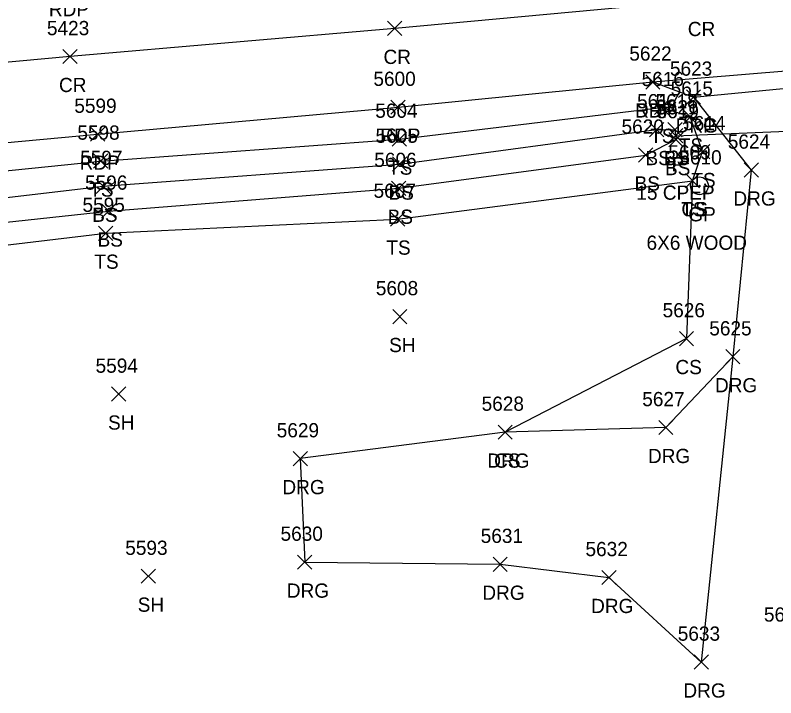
# Model space of a CAD drawing. Extents: x 1443912 to 1445411, y 621446 to 623693.
# Drawn here: x 1444289.1 to 1444396, y 622435.9 to 622531.9 of the extents above; entities that cross this region are included whole.
import ezdxf

# ---------------------------------------------------------------- set-up
doc = ezdxf.new("R2010")
doc.units = 0
for name, color, linetype in [('D_A', 7, 'Continuous'), ('D_C', 7, 'Continuous'), ('D_I', 7, 'Continuous'), ('D_TIC', 7, 'Continuous'), ('DCP', 7, 'Continuous'), ('L_A', 7, 'Continuous'), ('L_I', 7, 'Continuous'), ('L_TIC', 7, 'Continuous'), ('LELB', 7, 'Continuous'), ('P_A', 7, 'Continuous'), ('P_I', 7, 'Continuous'), ('P_TIC', 7, 'Continuous'), ('PET', 7, 'Continuous'), ('PRC', 7, 'Continuous'), ('R_A', 7, 'Continuous'), ('R_C', 7, 'Continuous'), ('R_I', 7, 'Continuous'), ('R_TIC', 7, 'Continuous'), ('RDG', 7, 'Continuous'), ('RDP', 7, 'Continuous'), ('RGP', 7, 'Continuous')]:
    doc.layers.add(name, color=color, linetype=linetype)

msp = doc.modelspace()

# ---------------------------------------------------------------- linework, layer by layer
at = {"layer": 'D_TIC'}
for points in [[(1444380.93, 622513.94), (1444382.93, 622515.94)], [(1444382.93, 622513.94), (1444380.93, 622515.94)]]:
    msp.add_lwpolyline(points, dxfattribs=at)
at = {"layer": 'DCP'}
msp.add_lwpolyline([(1444381.93, 622514.94), (1444423.13, 622516.67)], dxfattribs=at)
at = {"layer": 'L_TIC'}
for points in [[(1444378.93, 622517.92), (1444380.93, 622519.92)], [(1444380.93, 622517.92), (1444378.93, 622519.92)], [(1444378.93, 622517.92), (1444380.93, 622519.92)], [(1444380.93, 622517.92), (1444378.93, 622519.92)], [(1444382.95, 622516.58), (1444384.95, 622518.58)], [(1444384.95, 622516.58), (1444382.95, 622518.58)], [(1444378.23, 622514.8), (1444380.23, 622516.8)], [(1444380.23, 622514.8), (1444378.23, 622516.8)], [(1444380.82, 622514.79), (1444382.82, 622516.79)], [(1444382.82, 622514.79), (1444380.82, 622516.79)], [(1444342.08, 622513.46), (1444344.08, 622515.46)], [(1444344.08, 622513.46), (1444342.08, 622515.46)], [(1444380.97, 622513.39), (1444382.97, 622515.39)], [(1444382.97, 622513.39), (1444380.97, 622515.39)], [(1444384.71, 622511.71), (1444386.71, 622513.71)], [(1444386.71, 622511.71), (1444384.71, 622513.71)], [(1444300.08, 622510.38), (1444302.08, 622512.38)], [(1444302.08, 622510.38), (1444300.08, 622512.38)], [(1444376.7, 622511.23), (1444378.7, 622513.23)], [(1444378.7, 622511.23), (1444376.7, 622513.23)], [(1444376.7, 622511.23), (1444378.7, 622513.23)], [(1444378.7, 622511.23), (1444376.7, 622513.23)], [(1444342.11, 622509.95), (1444344.11, 622511.95)], [(1444344.11, 622509.95), (1444342.11, 622511.95)], [(1444383.28, 622507.61), (1444385.28, 622509.61)], [(1444385.28, 622507.61), (1444383.28, 622509.61)], [(1444383.28, 622507.61), (1444385.28, 622509.61)], [(1444385.28, 622507.61), (1444383.28, 622509.61)], [(1444300.47, 622506.83), (1444302.47, 622508.83)], [(1444302.47, 622506.83), (1444300.47, 622508.83)], [(1444341.99, 622506.55), (1444343.99, 622508.55)], [(1444343.99, 622506.55), (1444341.99, 622508.55)], [(1444301.22, 622503.35), (1444303.22, 622505.35)], [(1444303.22, 622503.35), (1444301.22, 622505.35)], [(1444341.84, 622502.21), (1444343.84, 622504.21)], [(1444343.84, 622502.21), (1444341.84, 622504.21)], [(1444300.8, 622500.23), (1444302.8, 622502.23)], [(1444302.8, 622500.23), (1444300.8, 622502.23)], [(1444342.15, 622488.51), (1444344.15, 622490.51)], [(1444344.15, 622488.51), (1444342.15, 622490.51)], [(1444382.44, 622485.41), (1444384.44, 622487.41)], [(1444384.44, 622485.41), (1444382.44, 622487.41)], [(1444302.64, 622477.61), (1444304.64, 622479.61)], [(1444304.64, 622477.61), (1444302.64, 622479.61)], [(1444356.95, 622472.26), (1444358.95, 622474.26)], [(1444358.95, 622472.26), (1444356.95, 622474.26)], [(1444306.81, 622452), (1444308.81, 622454)], [(1444308.81, 622452), (1444306.81, 622454)]]:
    msp.add_lwpolyline(points, dxfattribs=at)
at = {"layer": 'LELB'}
for points in [[(1444115.2, 622494.89), (1444168.95, 622497.42), (1444211.15, 622502.44), (1444251.83, 622506.34), (1444301.08, 622511.38), (1444343.08, 622514.46), (1444379.93, 622518.92)], [(1444185.15, 622436.84), (1444194.75, 622460.13), (1444204.54, 622478.89), (1444215.9, 622488.4), (1444251.49, 622495.26), (1444301.8, 622501.23), (1444342.84, 622503.21), (1444384.28, 622508.61), (1444385.71, 622512.71), (1444383.95, 622517.58), (1444379.93, 622518.92)], [(1444137.9, 622478.21), (1444124.84, 622486.58), (1444113.1, 622488.96), (1444113.21, 622490.09), (1444168.95, 622494.43), (1444215.67, 622499.54), (1444251.54, 622502), (1444301.47, 622507.83), (1444343.11, 622510.95), (1444379.23, 622515.8), (1444381.82, 622515.79), (1444381.97, 622514.39), (1444377.7, 622512.23)], [(1444185.61, 622491.47), (1444215.88, 622495.41), (1444251.8, 622498.9), (1444302.22, 622504.35), (1444342.99, 622507.55), (1444377.7, 622512.23)], [(1444384.28, 622508.61), (1444383.44, 622486.41), (1444357.95, 622473.26)]]:
    msp.add_lwpolyline(points, dxfattribs=at)
at = {"layer": 'P_TIC'}
for points in [[(1444341.42, 622529.03), (1444343.42, 622531.03)], [(1444343.42, 622529.03), (1444341.42, 622531.03)], [(1444295.8, 622525.08), (1444297.8, 622527.08)], [(1444297.8, 622525.08), (1444295.8, 622527.08)], [(1444377.71, 622521.5), (1444379.71, 622523.5)], [(1444379.71, 622521.5), (1444377.71, 622523.5)], [(1444341.9, 622517.95), (1444343.9, 622519.95)], [(1444343.9, 622517.95), (1444341.9, 622519.95)], [(1444299.66, 622514.16), (1444301.66, 622516.16)], [(1444301.66, 622514.16), (1444299.66, 622516.16)]]:
    msp.add_lwpolyline(points, dxfattribs=at)
at = {"layer": 'PET'}
msp.add_lwpolyline([(1443922.89, 622481.78), (1443964.16, 622485.92), (1444013.47, 622490.18), (1444063.08, 622494.61), (1444083.54, 622496.56), (1444116.52, 622499.25), (1444168.09, 622503.58), (1444210.27, 622507.18), (1444250.99, 622510.56), (1444300.66, 622515.16), (1444342.9, 622518.95), (1444378.71, 622522.5), (1444430.26, 622526.78), (1444460.19, 622529.88), (1444494.98, 622532.7), (1444537.07, 622536.56), (1444563.09, 622539.1), (1444595.4, 622542.11), (1444628.15, 622544.68), (1444676.42, 622546.88), (1444682.73, 622544.1), (1444699.24, 622535.04), (1444703.98, 622527.2), (1444703.26, 622510.63)], dxfattribs=at)
at = {"layer": 'PRC'}
msp.add_lwpolyline([(1444719.77, 622561.99), (1444681.72, 622559.72), (1444650.83, 622557.58), (1444613.8, 622554.84), (1444583.05, 622552.28), (1444545.98, 622548.57), (1444490.19, 622543.66), (1444448.69, 622540.02), (1444415.77, 622536.99), (1444385.19, 622533.95), (1444342.42, 622530.03), (1444296.8, 622526.08), (1444247.95, 622521.6), (1444210.22, 622518.45), (1444165.33, 622514.18), (1444110.47, 622509.68), (1444063.9, 622505.59), (1444012.84, 622501.59), (1443966.33, 622497.17), (1443919.63, 622492.61)], dxfattribs=at)
at = {"layer": 'R_TIC'}
for points in [[(1444377.71, 622521.5), (1444379.71, 622523.5)], [(1444379.71, 622521.5), (1444377.71, 622523.5)], [(1444383.42, 622519.38), (1444385.42, 622521.38)], [(1444385.42, 622519.38), (1444383.42, 622521.38)], [(1444383.42, 622519.38), (1444385.42, 622521.38)], [(1444385.42, 622519.38), (1444383.42, 622521.38)], [(1444391.55, 622509.12), (1444393.55, 622511.12)], [(1444393.55, 622509.12), (1444391.55, 622511.12)], [(1444388.95, 622482.86), (1444390.95, 622484.86)], [(1444390.95, 622482.86), (1444388.95, 622484.86)], [(1444388.95, 622482.86), (1444390.95, 622484.86)], [(1444390.95, 622482.86), (1444388.95, 622484.86)], [(1444379.53, 622472.91), (1444381.53, 622474.91)], [(1444381.53, 622472.91), (1444379.53, 622474.91)], [(1444356.95, 622472.26), (1444358.95, 622474.26)], [(1444358.95, 622472.26), (1444356.95, 622474.26)], [(1444328.16, 622468.53), (1444330.16, 622470.53)], [(1444330.16, 622468.53), (1444328.16, 622470.53)], [(1444328.77, 622453.98), (1444330.77, 622455.98)], [(1444330.77, 622453.98), (1444328.77, 622455.98)], [(1444356.25, 622453.68), (1444358.25, 622455.68)], [(1444358.25, 622453.68), (1444356.25, 622455.68)], [(1444371.54, 622451.82), (1444373.54, 622453.82)], [(1444373.54, 622451.82), (1444371.54, 622453.82)], [(1444384.51, 622439.93), (1444386.51, 622441.93)], [(1444386.51, 622439.93), (1444384.51, 622441.93)], [(1444384.51, 622439.93), (1444386.51, 622441.93)], [(1444386.51, 622439.93), (1444384.51, 622441.93)]]:
    msp.add_lwpolyline(points, dxfattribs=at)
at = {"layer": 'RDG'}
for points in [[(1444384.42, 622520.38), (1444392.55, 622510.12), (1444389.95, 622483.86), (1444385.51, 622440.93)], [(1444389.95, 622483.86), (1444380.53, 622473.91), (1444357.95, 622473.26), (1444329.16, 622469.53), (1444329.77, 622454.98), (1444357.25, 622454.68), (1444372.54, 622452.82), (1444385.51, 622440.93)]]:
    msp.add_lwpolyline(points, dxfattribs=at)
at = {"layer": 'RDP'}
msp.add_lwpolyline([(1444378.71, 622522.5), (1444384.42, 622520.38), (1444401.39, 622522.01), (1444424.34, 622524.73), (1444430.26, 622526.78)], dxfattribs=at)
at = {"layer": 'RGP'}
msp.add_line((1444385.26, 622507.9), (1444385.26, 622507.9), dxfattribs=at)
for radius in [1.25, 0.0833]:
    msp.add_circle((1444385.26, 622507.9), radius, dxfattribs=at)

# ---------------------------------------------------------------- texts
at = {"layer": 'D_A'}
msp.add_text('P', height=2, dxfattribs=at).set_placement((1444381.31, 622509.94))
at = {"layer": 'D_C'}
msp.add_text('15 CPEP', height=2, dxfattribs=at).set_placement((1444376.39, 622505.94))
at = {"layer": 'D_I'}
msp.add_text('5621', height=2, dxfattribs=at).set_placement((1444379.19, 622517.94))
at = {"layer": 'L_A'}
for s, p in [('TS', (1444378.34, 622513.92)), ('TS', (1444378.34, 622513.92)), ('TS', (1444382.36, 622512.58)), ('BS', (1444377.67, 622510.8)), ('BS', (1444380.26, 622510.79)), ('TS', (1444341.49, 622509.46)), ('BS', (1444380.41, 622509.39)), ('BS', (1444376.14, 622507.23)), ('BS', (1444376.14, 622507.23)), ('TS', (1444384.12, 622507.71)), ('TS', (1444299.49, 622506.38)), ('BS', (1444341.56, 622505.95)), ('BS', (1444299.91, 622502.83)), ('TS', (1444382.69, 622503.61)), ('CS', (1444382.72, 622503.61)), ('BS', (1444341.43, 622502.55)), ('BS', (1444300.66, 622499.35)), ('TS', (1444341.25, 622498.21)), ('TS', (1444300.21, 622496.23)), ('SH', (1444341.64, 622484.51)), ('CS', (1444381.88, 622481.41)), ('SH', (1444302.13, 622473.61)), ('CS', (1444356.39, 622468.26)), ('SH', (1444306.3, 622448))]:
    msp.add_text(s, height=2, dxfattribs=at).set_placement(p)
at = {"layer": 'L_I'}
for s, p in [('5616', (1444377.13, 622521.92)), ('5616', (1444377.13, 622521.92)), ('5615', (1444381.21, 622520.58)), ('5617', (1444376.49, 622518.8)), ('5618', (1444379.08, 622518.79)), ('5604', (1444339.69, 622517.46)), ('5619', (1444379.23, 622517.39)), ('5614', (1444382.97, 622515.71)), ('5620', (1444374.31, 622515.23)), ('5620', (1444374.31, 622515.23)), ('5598', (1444297.82, 622514.38)), ('5605', (1444339.73, 622513.95)), ('5609', (1444380.89, 622511.61)), ('5609', (1444380.89, 622511.61)), ('5597', (1444298.21, 622510.83)), ('5606', (1444339.55, 622510.55)), ('5596', (1444298.9, 622507.35)), ('5607', (1444339.45, 622506.21)), ('5595', (1444298.54, 622504.23)), ('5608', (1444339.77, 622492.51)), ('5626', (1444380.08, 622489.41)), ('5594', (1444300.38, 622481.61)), ('5628', (1444354.64, 622476.26)), ('5593', (1444304.55, 622456))]:
    msp.add_text(s, height=2, dxfattribs=at).set_placement(p)
at = {"layer": 'P_A'}
for s, p in [('RDP', (1444293.82, 622531.74)), ('CR', (1444383.62, 622528.95)), ('CR', (1444340.85, 622525.03)), ('CR', (1444295.24, 622521.08)), ('RDP', (1444376.2, 622517.5)), ('RDP', (1444340.39, 622513.95)), ('RDP', (1444298.14, 622510.16))]:
    msp.add_text(s, height=2, dxfattribs=at).set_placement(p)
at = {"layer": 'P_I'}
for s, p in [('5423', (1444293.54, 622529.08)), ('5622', (1444375.4, 622525.5)), ('5600', (1444339.43, 622521.95)), ('5599', (1444297.39, 622518.16)), ('5634', (1444394.32, 622446.62))]:
    msp.add_text(s, height=2, dxfattribs=at).set_placement(p)
at = {"layer": 'R_A'}
for s, p in [('DRP', (1444376.2, 622517.5)), ('DRG', (1444381.91, 622515.38)), ('DRP', (1444381.91, 622515.38)), ('DRG', (1444390.03, 622505.12)), ('GP', (1444383.69, 622502.9)), ('DRG', (1444387.44, 622478.86)), ('DRG', (1444387.44, 622478.86)), ('DRG', (1444378.02, 622468.91)), ('DRG', (1444355.44, 622468.26)), ('DRG', (1444326.64, 622464.53)), ('DRG', (1444327.26, 622449.98)), ('DRG', (1444354.74, 622449.68)), ('DRG', (1444370.03, 622447.82)), ('DRG', (1444383, 622435.93)), ('DRG', (1444383, 622435.93))]:
    msp.add_text(s, height=2, dxfattribs=at).set_placement(p)
at = {"layer": 'R_C'}
msp.add_text('6X6 WOOD', height=2, dxfattribs=at).set_placement((1444377.82, 622498.9))
at = {"layer": 'R_I'}
for s, p in [('5622', (1444375.4, 622525.5)), ('5623', (1444381.11, 622523.38)), ('5623', (1444381.11, 622523.38)), ('5624', (1444389.24, 622513.12)), ('5610', (1444382.43, 622510.9)), ('5625', (1444386.64, 622486.86)), ('5625', (1444386.64, 622486.86)), ('5628', (1444354.64, 622476.26)), ('5627', (1444377.22, 622476.91)), ('5629', (1444325.84, 622472.53)), ('5630', (1444326.38, 622457.98)), ('5631', (1444354.51, 622457.68)), ('5632', (1444369.24, 622455.82)), ('5633', (1444382.21, 622443.93)), ('5633', (1444382.21, 622443.93))]:
    msp.add_text(s, height=2, dxfattribs=at).set_placement(p)

doc.saveas('drawing.dxf')
